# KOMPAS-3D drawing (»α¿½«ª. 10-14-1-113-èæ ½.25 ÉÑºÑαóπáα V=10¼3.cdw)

Views: Вид 2
Referenced files: КМ-3.cdw
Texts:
  АС Маша
  ООО Северный Стандарт
  Текст на чертеже
  Размерные надписи
  Шероховатость
  Линия-выноска #1
  Линия-выноска #2
  Линия-выноска #3
  Отклонения формы и база
  Заголовок таблицы
  Ячейка таблицы
  Стрелка вида
  Обозначение изменения
  Фигурная скобка
  Номер узла
  Марка координационной оси
  VRCB
  Выносная надпись
  Обозначение узла
  Марка/позиционное обозначение с линией-выноской
  Марка/позиционное обозначение на линии
  Марка/позиционное обозначение без линии-выноски
  Normal
  txt
  Body Text
  heading 1
  Знак Знак Знак Знак Знак Знак
  Verdana
  Лит-Масса-Масштаб
  Материал-Предприятие
  MS Sans Serif
  Simplex
  Txt
  Title Specification
  Body Specification ( left align )
  Body Specificaton ( centered )
  Без имени
  TXT
  Additional DXF text style 0
  Обычный
  Термин
  Список определений
  Адрес
  Цитаты
  Форматированный
  Courier New
  Z-конец формы
  Z-начало формы
  ТекстШаг1
  ООббыыччнныыйй
  Definition Term
  Definition List
  Address
  Blockquote
  Preformatted
  z-Bottom of Form
  z-Top of Form
  ISOCP
  Денис
  Title
  header
  heading 2
  AGOpus
  footer
  HeliosLight
  Pa3
  Pa1
  ссылки
  Подпись в квадратике
  табл
  цепи
  Маркировка
  клеммы, контакты
  тексты табл
  Тексты. 3,2
  ЗОНА_привяз
  текст переноса
  ТТееррммиинн
  ССппииссоокк ооппррееддееллеенниийй
  ААддрреесс
  ЦЦииттааттыы
  ФФооррммааттиирроовваанннныыйй
  Z-ккооннеецц ффооррммыы
  Z-ннааччааллоо ффооррммыы
  GOST 2.304 type A
  rustxt
  heading 8
  heading 3
  heading 6
  heading 7
  russ
  Абзац Знак
  heading 4
  heading 5
  heading 9
  Body Text 3
  Шрифт 2.5
  Заголовки
  RUSTXT
  ISOCPEUR
  FR5
  Tahoma
  Table Heading
  Table Contents
  маркировка
  NormalParagraphStyle
  ESK - Обозначение
  ГОСТ_МНЕ
  II 5
  Iiaioieo 4
  Ioieo 3
  Iia?acaae 2
  ?acaae 1
  Ciae Ciae Ciae Ciae Ciae Ciae
  MONOMAKH
  Heading
  HiddenHorzOCl
  CM2
  CM7
  CM3
  CM4
  CM8
  CM9
  style2
  Три с половиной
  Aioiaue
  Courier New Cyr
  CNBNDG+TimesNewRoman
  Subtitle
  Текст 3,5
  Helvetica
  CM97
  CM93
  Схема расположения резервуара
  Примечания:
  1. Резервуар предназначен для накопления очищенных стоков после их прохождения через
  очистную установку. Резервуар поставляется комплектно с очистной установкой.
  2. Крутизну откосов котлована заложить согласно СНиП 3.02.01.87.
  3. Обратную засыпку котлована выполнять песком средней крупности с послойным уплотнением.
  4. Перед установкой резервуара в проектное положение должна быть выполнена антикоррозионная
  защита поверхности резервуара.
  5. Резервуар устанавливается на анкерный бетонный фундамент. Крепление к фундаменту
  выполняется при помощи хомутов (размеры уточнить перед монтажом резервуара). На схеме
  расположения резервуара и разрезе 1-1 условно показан только один хомут. Их число и
  расстановка соответствует разбивке закладных деталей М-4.
  6. Зазор между стенкой резервуара и седлом фундамента заполнить цементным раствором М50.
  7. Место сопряжения резервуара с трубопроводом очищенного стока уточнить по месту.
  В качестве соединительного элемента применить стальную трубу  127 мм, длиной 500 мм
  по ГОСТ 10704-91. Места стыковки труб герметизировать. Стыковку трубы с резервуаром
  выполнить сваркой с последующей защитой открытых металлических частей соединения от
  коррозии. Соединение  труб ПЭ80 (ГОСТ 18599-2001) с металлическим резервуаром
  осуществляется с помощью стального сварного патрубка (ГОСТ 10704-91), соединение
  загерметизировать. Труба входит в резервуар на отметке - 0,95м (абсолютная отметка - 99,05м).
  (см. 10/14-1-028-НК, л.3)
  8. Мероприятия по утеплению корпуса проводит завод-изготовитель резервуара. В данном случае
  это будет двойной утепленный корпус, состоящий из двух стальных стенок, между которыми
  располагается утеплитель (минеральная вата на основе базальтового волокна).
  9. Над резервуаром помимо собственного веса грунта не допускаются иные постоянные или
  подвижные нагрузки.
  10. Относительная отметка 0,000 соответствует абсолютной отметке 100,00.
  11. Границы котлована показаны без учета конструкций крепления стенок. Схему монтажа
  резервуара см. 10/14-1-ПОС л.11.
  Х-2 (3 шт.)
  Отмостка из
  асфальто-бетона
  Х-2 (4 шт.)
  Марка,
  поз.
  Кол.
  ед. кг
  ГОСТ 103-2006
  ГОСТ 8509-93
  Хомут Х-2
  Анкерный фундамент Ф-3
  Закладная деталь М-4
  Бетон В15 F200 W6
  Резервуар
  См. примечание 5
  См. примечание 6
  См. примечание 7
  См. примечание 8
  Щебеночный балласт t=250мм
  фракция 20-40мм
  Болт М10 х 30
  ACAD_ISO10W100_RGB_0_0_0_SC_0.25_THICK_0.25
  ACAD_ISO04W100_RGB_0_0_0_SC_1_THICK_0.25
  ACAD_ISO10W100_RGB_0_0_0_SC_1_THICK_0.25
  ACAD_ISO10W100_RGB_0_0_0_SC_0.5_THICK_0.25
  ACAD_ISO10W100_RGB_255_0_0_SC_0.25_THICK_0.25
  СONTINUOUS_RGB_255_0_0_THICK_0.25
  POLYLINE_STYLE_0.25_RGB_40_0_0
  POLYLINE_STYLE_0.40_RGB_0_0_0
  ACAD_ISO10W100_RGB_40_0_0_SC_0.25_THICK_0.25
  ACAD_ISO04W100_RGB_40_0_0_SC_1_THICK_0.25
  ACAD_ISO10W100_RGB_40_0_0_SC_1_THICK_0.25
  AR-SAND
  AR-SAND 0
  AR-SAND 1
  AR-SAND 2
  AR-SAND 3
  Стили документа
  Разраб.
  Шашерин
  Королева
  Реконструкция ПС 110 кВ Опорная
  (замена трансформаторов 16МВА на 40МВА)
  Резервуар V=10м 3
  Галактионов
Dimensions and other numbers on the sheet: 10/14-1-113-КС; 7; 3.5; 2.5; 2,5; 1,8; 3,2_; 3,2; 2,5 (контакты, клеммы); 3,2 (надписи); 3,2 (Зоны); 5; 2,5_01; 2,5_3; 3,5_01; 3,5_tabl; 5_заголовок; 2,3_; 3,2_зона не привяз; 3,5; 3.2 маркировка; 3,2 элементы; 3,2 линия; 3,2 таблица; 2,5 грязносинь; 2.5 курсив; 2.5_Э5_надписи; 2.5_Э5_ссылки; 2.5_кабель; 3.2; 2.5 надписи; 3.2 фиол; 5,0_белый_подчёркнутый; 3 и 5; 3.2 (текст); 1; 2-2; 3; 3 (8 шт.); 0,000; 2; 4; 10/14-1-113-КС.И-11; 6; 36,5; 35,0; 0,75; 9,6; 2100; 7,0 м; 900; 1800; 1235; 2470; 1000; 3700; 4700; 700; 3450; 250; 4 (8 шт.); 563; 672; 335; 260; 1390; 1-1; 1344; -2,320; -3,270; 4470; 3-3; 1400; 950; 330; 1890; 1130; 1:100; 100; 50; 25; 06.08/86.002-КМ-; 11.12; 10.12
